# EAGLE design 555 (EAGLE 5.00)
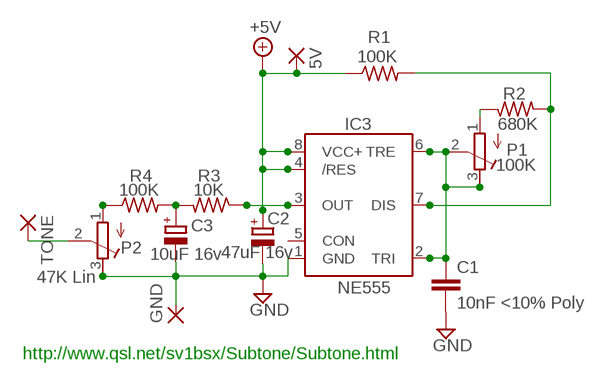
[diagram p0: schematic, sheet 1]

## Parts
5V  3,81/1,4  [3,81/1,4]
C1  10nF <10% Poly  C-EU050-030X075  [C050-030X075]
C2  47uF 16v  CPOL-EUE2-4  [E2-4]
C3  10uF 16v  CPOL-EUE2-4  [E2-4]
GND  3,81/1,4  [3,81/1,4]
IC3  NE555  [DIL-08]
P1  100K  R-TRIMM64W  [RTRIM64W]
P2  47K Lin  R-TRIMM64W  [RTRIM64W]
R1  100K  R-US_0204/7  [0204/7]
R2  680K  R-US_0204/7  [0204/7]
R3  10K  R-US_0204/7  [0204/7]
R4  100K  R-US_0204/7  [0204/7]
TONE  3,81/1,4  [3,81/1,4]

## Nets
+5V: 5V.1(P) C2.+ IC3.4(/RES) IC3.8(VCC+) R1.1
GND: C1.2 C2.- C3.- IC3.1(GND) P2.3(A)
N$1: C3.+ R3.2 R4.2
N$2: P2.1(E) R4.1
N$3: IC3.3(OUT) R3.1
N$5: IC3.7(DIS) R1.2 R2.2
N$6: P1.1(E) R2.1
N$7: C1.1 IC3.2(TRI) IC3.6(TRE) P1.2(S) P1.3(A)
N$8: P2.2(S) TONE.1(P)
Unconnected: GND.1(P) IC3.5(CON)

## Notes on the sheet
- http://www.qsl.net/sv1bsx/Subtone/Subtone.html

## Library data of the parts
5V GND TONE = wirepad:3,81/1,4: THROUGH-HOLE PAD
C1 = rcl:C-EU: CAPACITOR, European symbol
C2 C3 = rcl:CPOL-EU: POLARIZED CAPACITOR, European symbol
IC3 = st-microelectronics:NE555: General purpose bipolar Timer
P1 P2 = resistor:R-TRIMM: Trimm resistor
R1-R4 = resistor:R-US_: RESISTOR, American symbol

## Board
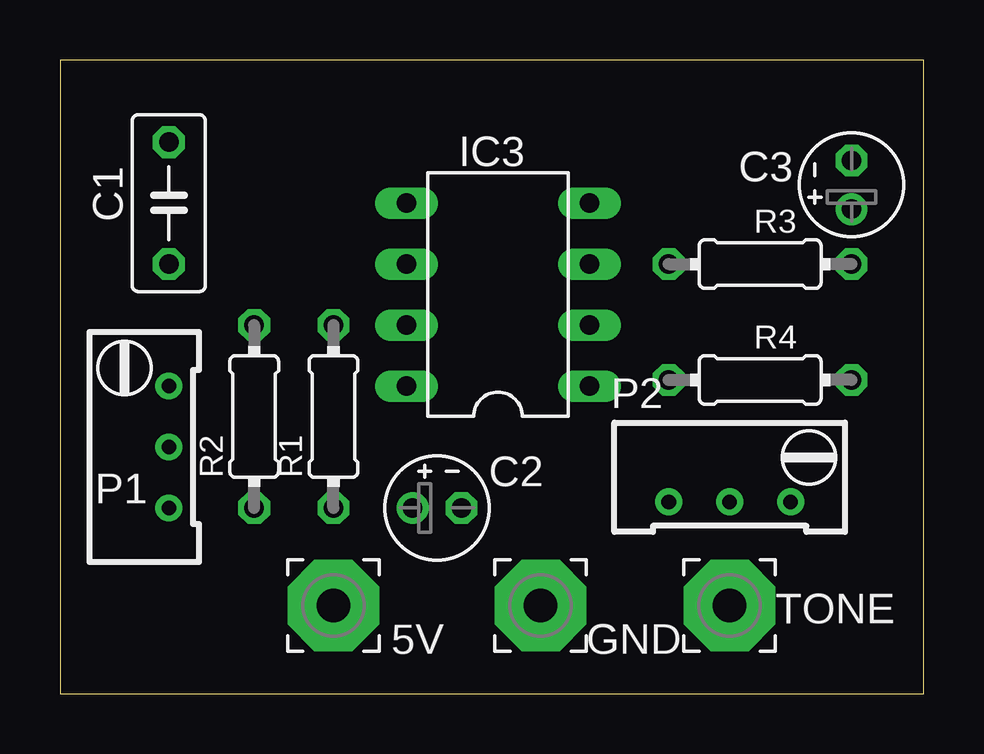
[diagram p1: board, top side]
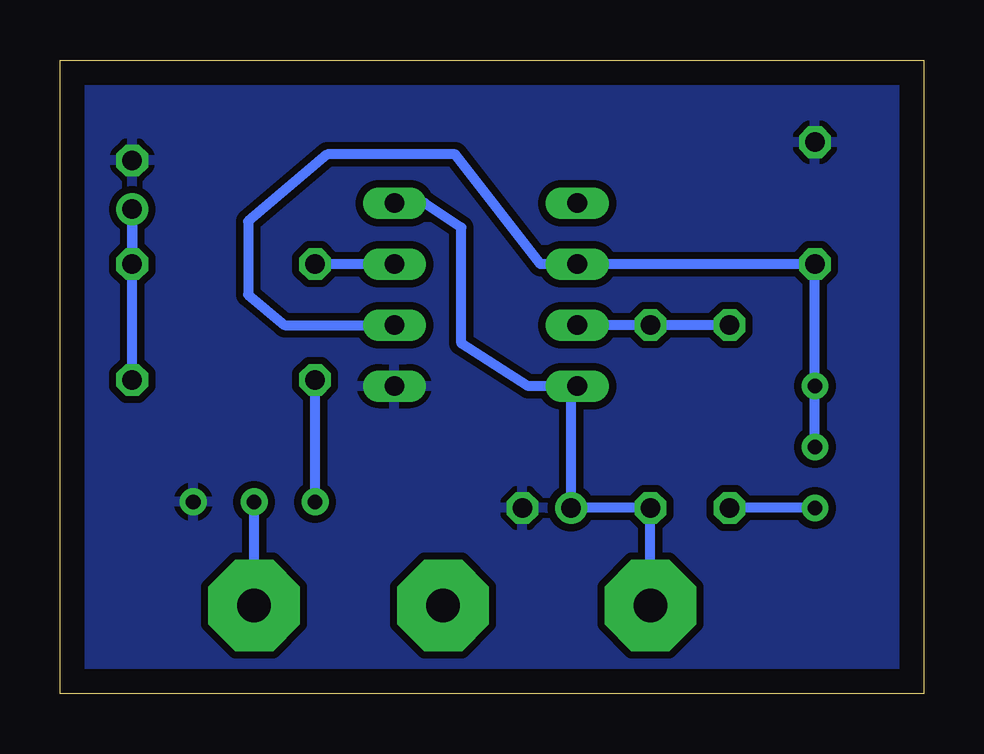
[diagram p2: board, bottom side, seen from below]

Size 35.99 x 26.41 mm. Coordinates in mm from the lower left corner, seen from the top.
Outline: 0,0 35.99,0 35.99,26.41 0,26.41 0,0
Copper layers (1*16): Top 0.035mm / dielectric 1.5mm / Bottom 0.035mm
Design rules "default": minimum track width 10mil, minimum drill 24mil, track to track 8mil, track to pad 8mil, pad to pad 8mil, via to via 8mil, smd to smd 8mil, copper to edge 40mil, drill to drill 8mil, minimum pad ring 10mil, minimum via ring 8mil, stop-mask expansion 4mil, vias tented up to drill 0mil, thermal gap 10mil

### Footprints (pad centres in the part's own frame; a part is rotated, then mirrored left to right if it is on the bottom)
3,81/1,4 = drill 1.397 pad 3.81 octagon: 1 0,0
C050-030X075 = drill 0.813 octagon: 1 -2.54,0; 2 2.54,0
E2-4 = drill 0.813 pad 1.27 round: + -1.016,0 | drill 0.813 pad 1.27 octagon: - 1.016,0
DIL-08 = drill 0.813 long: 1 -3.81,-3.81; 2 -1.27,-3.81; 3 1.27,-3.81; 4 3.81,-3.81; 5 3.81,3.81; 6 1.27,3.81; 7 -1.27,3.81; 8 -3.81,3.81
RTRIM64W = drill 0.61 round: 1 1.27,-2.54; 2 1.27,0; 3 1.27,2.54
0204/7 = drill 0.813 octagon: 1 -3.81,0; 2 3.81,0

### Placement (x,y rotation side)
5V  11.39,3.68 0 top
C1  4.53,20.44 90 top
C2  15.71,7.74 0 top
C3  32.98,21.2 90 top
GND  20.03,3.68 0 top
IC3  18.25,16.63 90 top
P1  3.26,10.28 0 top
P2  27.9,9.27 270 top
R1  11.39,11.55 90 top
R2  8.09,11.55 90 top
R3  29.17,17.9 0 top
R4  29.17,13.08 0 top
TONE  27.9,3.68 0 top

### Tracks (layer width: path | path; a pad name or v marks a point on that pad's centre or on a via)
+5V
  Bottom 0.406: 14.69,12.82 C2.+ R1.1 5V.1 | IC3.4 20.79,20.44 19.27,19.43 19.27,14.6 16.47,12.82 14.69,12.82 | 14.69,12.82 IC3.8
GND
  pour Bottom (isolate 0.305): -4.61,35.68 39.84,35.68 39.84,0.63 -4.61,0.63
N$1
  Bottom 0.406: R3.2 C3.+ R4.2
N$2
  Bottom 0.406: P2.1 R4.1
N$3
  Bottom 0.406: IC3.3 R3.1
N$5
  Bottom 0.406: IC3.7 R1.2 R2.2
N$6
  Bottom 0.406: P1.1 R2.1
N$7
  Bottom 0.406: P1.2 P1.3 C1.1 IC3.6 15.96,17.9 19.52,22.47 24.85,22.47 28.16,19.68 28.16,16.63 26.63,15.36 IC3.2
N$8
  Bottom 0.406: TONE.1 P2.2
